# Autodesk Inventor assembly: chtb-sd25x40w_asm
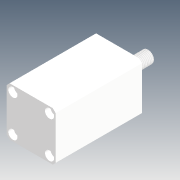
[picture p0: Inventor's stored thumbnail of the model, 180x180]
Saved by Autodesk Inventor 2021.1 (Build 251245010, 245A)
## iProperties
Company: Microsoft
Created: 2018-05
Part Number: chtb-sd25x40w_asm
Description: STEP AP214
Document SubType Name: Assembly
Designer: user
Title: chtb-sd25x40w_asm.STEP
Author: Windows
Revision Number: ÈÎºÎ
Sending System: SolidWorks 2015
Preprocessor: SwSTEP 2.0
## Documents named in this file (4)
- D:\Vault_2016\Projekty\Clamptek\Hydraulic\CHTB\CHTB-25\Inventor\chtb-sd25x40w\chtb-sd25x40w_asm.iam
- D:\Vault_2016\Projekty\Clamptek\Hydraulic\CHTB\CHTB-25\Inventor\chtb-sd25x40w\CHTB-25QG.ipt
- D:\Vault_2016\Projekty\Clamptek\Hydraulic\CHTB\CHTB-25\Inventor\chtb-sd25x40w\CHTB-SD25X40NBT.ipt
- D:\Vault_2016\Projekty\Clamptek\Hydraulic\CHTB\CHTB-25\Inventor\chtb-sd25x40w\CHTB-SD25X40WHSG.ipt
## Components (3 placed, 3 different names)
1. CHTB-25QG_1
2. CHTB-SD25X40NBT_2
3. CHTB-SD25X40WHSG_3
